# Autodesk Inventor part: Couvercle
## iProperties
Shininess: 64.0
Length Units: 11269
Angle Units: 11279
Time Units: 11290
Mass Units: 11283
Length Display Precision: 3
Angle Display Precision: 2
Compacted: True
Part Number: Couvercle
Document SubType Name: Modeling
Created: 2005-01
Material: Par défaut
Designer: Flavien MARTY
Density: 0.0
Volumn: 0.0
Area: 0.0
PropertySet Name: Model Information
Control State: 0
Master: False
Checked Out: False
Norme de conversion: STEP AP203
Nom du fichier: Couvercle.STEP
Préprocesseur: SolidWorks 2001039
Postprocesseur: Build: Release: 6 RTM Build: 90b - Date: Tue 09/24/2002
Unités envoyées: MILLIMETERS
Incertitude: 0.0
Author: Flavien MARTY
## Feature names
1. Base1
